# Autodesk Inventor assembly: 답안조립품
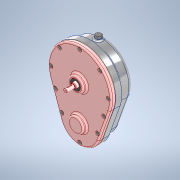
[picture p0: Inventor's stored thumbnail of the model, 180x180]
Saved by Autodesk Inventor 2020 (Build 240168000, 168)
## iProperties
Created: 2024-05
Part Number: 답안조립품
Document SubType Name: Assembly
Designer: oem
Author: oem
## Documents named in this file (13)
- C:\Users\oem\Desktop\740504V1004\답안조립품.iam
- C:\Users\oem\Desktop\740504V1004\본체.ipt
- C:\Users\oem\Desktop\740504V1004\오일리스 부시.ipt
- C:\Users\oem\Desktop\740504V1004\상단 축.ipt
- C:\Users\oem\Desktop\740504V1004\평행키 5x5x12.ipt
- C:\Users\oem\Desktop\740504V1004\스퍼기어A.ipt
- C:\Users\oem\Desktop\740504V1004\하단 축.ipt
- C:\Users\oem\Desktop\740504V1004\스퍼기어B.ipt
- C:\Users\oem\Desktop\740504V1004\가스켓.ipt
- C:\Users\oem\Desktop\740504V1004\커버.ipt
- C:\Users\oem\Desktop\740504V1004\육각 소켓 머리 볼트 M4x10.ipt
- C:\Users\oem\Desktop\740504V1004\오일 실 10 20 4.ipt
- C:\Users\oem\Desktop\740504V1004\육각 머리 볼트  M6x0.75x6.ipt
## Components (2 placed, 2 different names)
1. 하단 축:1 — 각도:3
2. 가스켓:1
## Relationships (1: Angle 1)
- 각도:3 [Angle]: 하단 축:1
